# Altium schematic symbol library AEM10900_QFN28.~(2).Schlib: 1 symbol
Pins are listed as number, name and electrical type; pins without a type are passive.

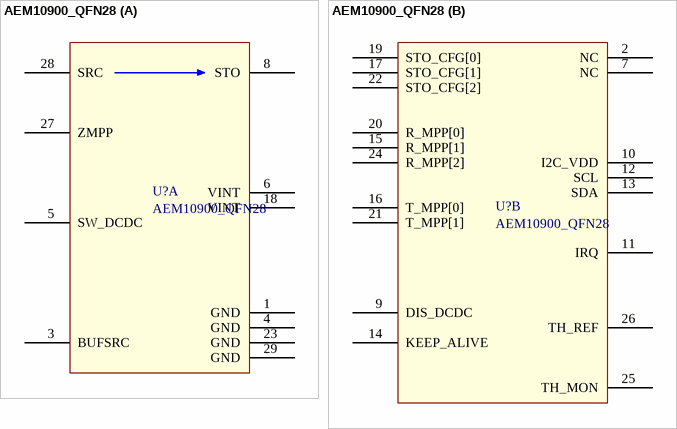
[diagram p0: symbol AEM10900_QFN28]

## AEM10900_QFN28
designator U?
footprint QFN28 4x4mm pitch=0.4mm Pad_0.23mm TPad 2.3mm (QFN, 28-Leads, Body 4.00x4.00mm, Pitch 0.40mm, Thermal Pad 2.60x2.60mm, IPC Medium Density)
part A pins: 1 GND, 3 BUFSRC, 4 GND, 5 SW_DCDC, 6 VINT, 8 STO, 18 VINT, 23 GND, 27 ZMPP, 28 SRC (power), 29 GND
part B pins: 2 NC, 7 NC, 9 DIS_DCDC, 10 I2C_VDD, 11 IRQ, 12 SCL, 13 SDA, 14 KEEP_ALIVE, 15 R_MPP[1], 16 T_MPP[0], 17 STO_CFG[1], 19 STO_CFG[0], 20 R_MPP[0], 21 T_MPP[1], 22 STO_CFG[2], 24 R_MPP[2], 25 TH_MON, 26 TH_REF (power)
